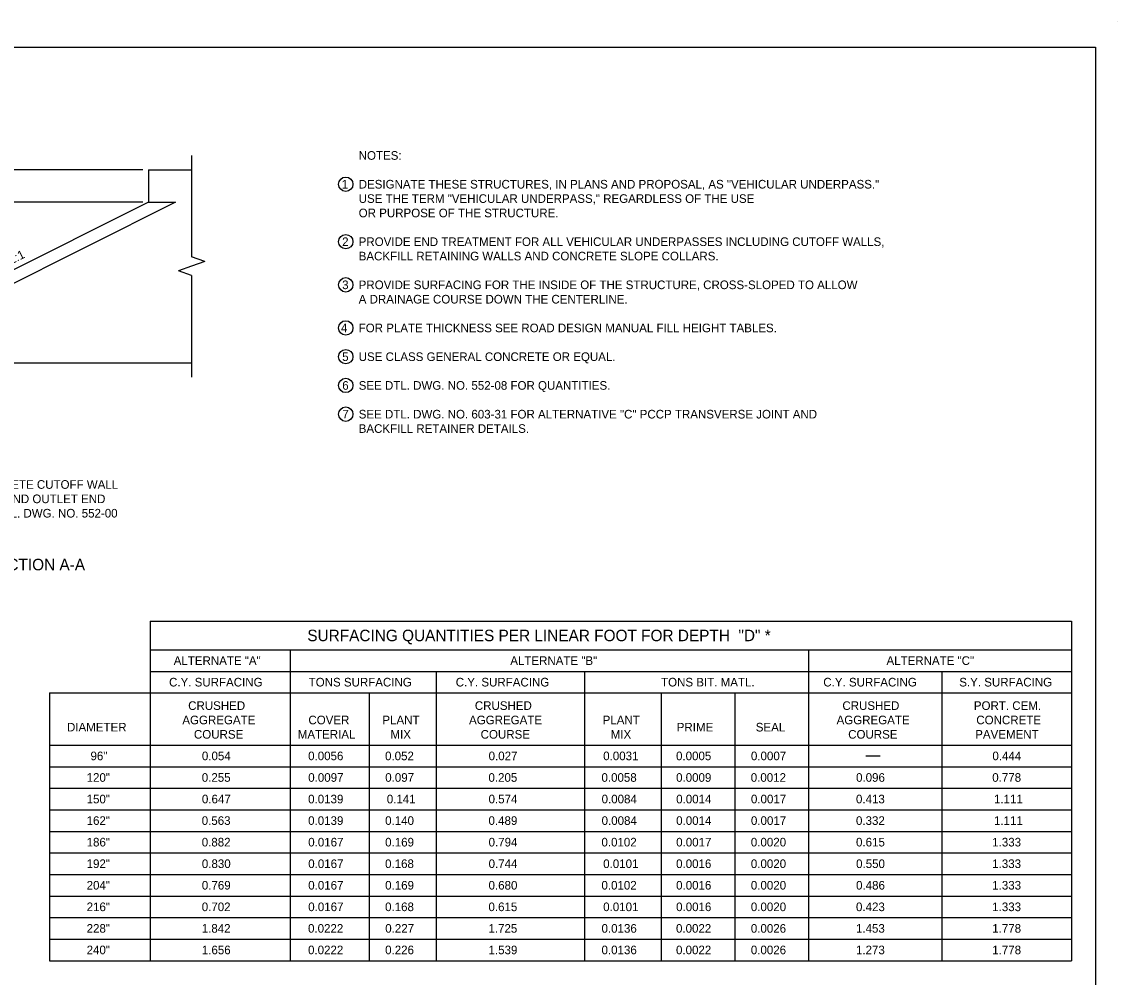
# Model space of a CAD drawing. Extents: x 49991.4 to 50021, y 49987.6 to 50011.4.
# Drawn here: x 50009.28 to 50016.9, y 49992.53 to 49999.18 of the extents above; entities that cross this region are included whole.
import ezdxf

# ---------------------------------------------------------------- set-up
doc = ezdxf.new("R2010")
doc.units = 0
for name, color, linetype in [('Level 1', 7, 'Continuous'), ('Level 2', 7, 'Continuous'), ('Level 3', 7, 'Continuous'), ('Level 6', 7, 'Continuous')]:
    doc.layers.add(name, color=color, linetype=linetype)

msp = doc.modelspace()

# ---------------------------------------------------------------- linework, layer by layer
at = {"layer": 'Level 1'}
for p, q in [((50016.9001, 49999.1756), (50016.9001, 49999.1756)), ((50010.1574, 49998.1464), (50010.1574, 49997.9206)), ((50010.1574, 49998.1464), (50010.4571, 49998.1464)), ((50010.1574, 49997.9206), (50008.3776, 49997.0307)), ((50010.3438, 49997.9206), (50008.4946, 49996.996)), ((50010.1574, 49997.9206), (50010.3438, 49997.9206)), ((50008.4946, 49996.8045), (50010.4571, 49996.8045))]:
    msp.add_line(p, q, dxfattribs=at)
msp.add_lwpolyline([(49999.3835, 49998.9992), (50016.7501, 49998.9992), (50016.7501, 49987.7988), (49999.3835, 49987.7988)], close=True, dxfattribs=at)
at = {"layer": 'Level 2'}
for p, q in [((50010.168, 49995.0069), (50016.5817, 49995.0069)), ((50010.168, 49995.0069), (50010.168, 49992.6438)), ((50016.5817, 49995.0069), (50016.5817, 49992.6438)), ((50010.168, 49994.8069), (50016.5817, 49994.8069)), ((50011.1426, 49994.8069), (50011.1426, 49992.6438)), ((50014.7527, 49994.8069), (50014.7527, 49992.6438)), ((50010.168, 49994.6569), (50016.5817, 49994.6569)), ((50012.1585, 49994.6569), (50012.1585, 49992.6438)), ((50013.1912, 49994.6569), (50013.1912, 49992.6438)), ((50015.6807, 49994.6569), (50015.6807, 49992.6438)), ((50009.468, 49994.5069), (50016.5817, 49994.5069)), ((50009.468, 49994.5069), (50009.468, 49992.6438)), ((50011.6938, 49994.5069), (50011.6938, 49992.6438)), ((50013.7256, 49994.5069), (50013.7256, 49992.6438)), ((50014.2383, 49994.5069), (50014.2383, 49992.6438)), ((50009.468, 49994.1438), (50016.5817, 49994.1438)), ((50015.1505, 49994.0688), (50015.2496, 49994.0688)), ((50009.468, 49993.9938), (50016.5817, 49993.9938)), ((50009.468, 49993.8438), (50016.5817, 49993.8438)), ((50009.468, 49993.6938), (50016.5817, 49993.6938)), ((50009.468, 49993.5438), (50016.5817, 49993.5438)), ((50009.468, 49993.3938), (50016.5817, 49993.3938)), ((50009.468, 49993.2438), (50016.5817, 49993.2438)), ((50009.468, 49993.0938), (50016.5817, 49993.0938)), ((50009.468, 49992.9438), (50016.5817, 49992.9438)), ((50009.468, 49992.7938), (50016.5817, 49992.7938)), ((50009.468, 49992.6438), (50016.5817, 49992.6438))]:
    msp.add_line(p, q, dxfattribs=at)
for centre in [(50011.5303, 49998.0464), (50011.5303, 49997.6464), (50011.5303, 49997.3464), (50011.5303, 49997.0464), (50011.5303, 49996.8464), (50011.5303, 49996.6464), (50011.5303, 49996.4464)]:
    msp.add_circle(centre, 0.05, dxfattribs=at)
at = {"layer": 'Level 3'}
for p, q in [((50010.1174, 49998.1464), (50008.0477, 49998.1464)), ((50010.1174, 49997.9206), (50008.0477, 49997.9206))]:
    msp.add_line(p, q, dxfattribs=at)
at = {"layer": 'Level 6'}
for p, q in [((50010.4571, 49998.2464), (50010.4571, 49997.5402)), ((50010.5485, 49997.5078), (50010.4571, 49997.5402)), ((50010.4571, 49997.4754), (50010.3657, 49997.443)), ((50010.5485, 49997.5078), (50010.4571, 49997.4754)), ((50010.4571, 49997.4106), (50010.3657, 49997.443)), ((50010.4571, 49997.4106), (50010.4571, 49996.7045))]:
    msp.add_line(p, q, dxfattribs=at)

# ---------------------------------------------------------------- texts
at = {"layer": 'Level 2'}
for s, height, p in [('NOTES:', 0.06, (50011.6203, 49998.2164)), ('1', 0.06, (50011.5017, 49998.0164)), ('DESIGNATE THESE STRUCTURES, IN PLANS AND PROPOSAL, AS "VEHICULAR UNDERPASS."', 0.06, (50011.6203, 49998.0164)), ('USE THE TERM "VEHICULAR UNDERPASS," REGARDLESS OF THE USE', 0.06, (50011.6203, 49997.9164)), ('OR PURPOSE OF THE STRUCTURE.', 0.06, (50011.6203, 49997.8164)), ('2', 0.06, (50011.5051, 49997.6164)), ('PROVIDE END TREATMENT FOR ALL VEHICULAR UNDERPASSES INCLUDING CUTOFF WALLS,', 0.06, (50011.6203, 49997.6164)), ('BACKFILL RETAINING WALLS AND CONCRETE SLOPE COLLARS.', 0.06, (50011.6203, 49997.5164)), ('3', 0.06, (50011.5051, 49997.3164)), ('PROVIDE SURFACING FOR THE INSIDE OF THE STRUCTURE, CROSS-SLOPED TO ALLOW', 0.06, (50011.6203, 49997.3164)), ('A DRAINAGE COURSE DOWN THE CENTERLINE.', 0.06, (50011.6203, 49997.2164)), ('4', 0.06, (50011.4966, 49997.0164)), ('FOR PLATE THICKNESS SEE ROAD DESIGN MANUAL FILL HEIGHT TABLES.', 0.06, (50011.6203, 49997.0164)), ('5', 0.06, (50011.5054, 49996.8164)), ('USE CLASS GENERAL CONCRETE OR EQUAL.', 0.06, (50011.6203, 49996.8164)), ('6', 0.06, (50011.5058, 49996.6164)), ('SEE DTL. DWG. NO. 552-08 FOR QUANTITIES.', 0.06, (50011.6203, 49996.6164)), ('7', 0.06, (50011.5065, 49996.4164)), ('SEE DTL. DWG. NO. 603-31 FOR ALTERNATIVE "C" PCCP TRANSVERSE JOINT AND', 0.06, (50011.6203, 49996.4164)), ('BACKFILL RETAINER DETAILS.', 0.06, (50011.6203, 49996.3164)), ('CONCRETE CUTOFF WALL', 0.06, (50008.9074, 49995.9273)), ('INLET AND OUTLET END', 0.06, (50008.9074, 49995.8273)), ('SEE DTL. DWG. NO. 552-00', 0.06, (50008.9074, 49995.7273)), ('SECTION A-A', 0.08, (50009.0318, 49995.3602)), ('SURFACING QUANTITIES PER LINEAR FOOT FOR DEPTH  "D" *', 0.08, (50011.2625, 49994.8669)), ('ALTERNATE "A"', 0.06, (50010.3325, 49994.7019)), ('ALTERNATE "B"', 0.06, (50012.6756, 49994.7019)), ('ALTERNATE "C"', 0.06, (50015.2947, 49994.7019)), ('C.Y. SURFACING', 0.06, (50010.3001, 49994.5519)), ('TONS SURFACING', 0.06, (50011.2721, 49994.5519)), ('C.Y. SURFACING', 0.06, (50012.2961, 49994.5519)), ('TONS BIT. MATL.', 0.06, (50013.7255, 49994.5519)), ('C.Y. SURFACING', 0.06, (50014.8548, 49994.5519)), ('S.Y. SURFACING', 0.06, (50015.8012, 49994.5519)), ('CRUSHED', 0.06, (50010.4331, 49994.3888)), ('CRUSHED', 0.06, (50012.429, 49994.3888)), ('CRUSHED', 0.06, (50014.9878, 49994.3888)), ('PORT. CEM.', 0.06, (50015.9029, 49994.3888)), ('AGGREGATE', 0.06, (50010.3925, 49994.2888)), ('COVER', 0.06, (50011.2702, 49994.2888)), ('PLANT', 0.06, (50011.7851, 49994.2888)), ('AGGREGATE', 0.06, (50012.3885, 49994.2888)), ('PLANT', 0.06, (50013.3185, 49994.2888)), ('AGGREGATE', 0.06, (50014.9473, 49994.2888)), ('CONCRETE', 0.06, (50015.92, 49994.2888)), ('DIAMETER', 0.06, (50009.5896, 49994.2388)), ('PRIME', 0.06, (50013.8345, 49994.2388)), ('SEAL', 0.06, (50014.3847, 49994.2388)), ('COURSE', 0.06, (50010.4733, 49994.1888)), ('MATERIAL', 0.06, (50011.1963, 49994.1888)), ('MIX', 0.06, (50011.8415, 49994.1888)), ('COURSE', 0.06, (50012.4693, 49994.1888)), ('MIX', 0.06, (50013.3749, 49994.1888)), ('COURSE', 0.06, (50015.0281, 49994.1888)), ('PAVEMENT', 0.06, (50015.9124, 49994.1888)), ('96"', 0.06, (50009.7531, 49994.0388)), ('0.054', 0.06, (50010.5287, 49994.0388)), ('0.0056', 0.06, (50011.2683, 49994.0388)), ('0.052', 0.06, (50011.8037, 49994.0388)), ('0.027', 0.06, (50012.5248, 49994.0388)), ('0.0031', 0.06, (50013.3225, 49994.0388)), ('0.0005', 0.06, (50013.8295, 49994.0388)), ('0.0007', 0.06, (50014.351, 49994.0388)), ('0.444', 0.06, (50016.032, 49994.0388)), ('120"', 0.06, (50009.7262, 49993.8888)), ('0.255', 0.06, (50010.5277, 49993.8888)), ('0.0097', 0.06, (50011.269, 49993.8888)), ('0.097', 0.06, (50011.8051, 49993.8888)), ('0.205', 0.06, (50012.5237, 49993.8888)), ('0.0058', 0.06, (50013.3104, 49993.8888)), ('0.0009', 0.06, (50013.8299, 49993.8888)), ('0.0012', 0.06, (50014.3496, 49993.8888)), ('0.096', 0.06, (50015.0828, 49993.8888)), ('0.778', 0.06, (50016.031, 49993.8888)), ('150"', 0.06, (50009.7262, 49993.7388)), ('0.647', 0.06, (50010.5288, 49993.7388)), ('0.0139', 0.06, (50011.2683, 49993.7388)), ('0.141', 0.06, (50011.8159, 49993.7388)), ('0.574', 0.06, (50012.5246, 49993.7388)), ('0.0084', 0.06, (50013.3114, 49993.7388)), ('0.0014', 0.06, (50013.8305, 49993.7388)), ('0.0017', 0.06, (50014.351, 49993.7388)), ('0.413', 0.06, (50015.0822, 49993.7388)), ('1.111', 0.06, (50016.0429, 49993.7388)), ('162"', 0.06, (50009.7262, 49993.5888)), ('0.563', 0.06, (50010.5274, 49993.5888)), ('0.0139', 0.06, (50011.2683, 49993.5888)), ('0.140', 0.06, (50011.8045, 49993.5888)), ('0.489', 0.06, (50012.524, 49993.5888)), ('0.0084', 0.06, (50013.3114, 49993.5888)), ('0.0014', 0.06, (50013.8305, 49993.5888)), ('0.0017', 0.06, (50014.351, 49993.5888)), ('0.332', 0.06, (50015.0822, 49993.5888)), ('1.111', 0.06, (50016.0429, 49993.5888)), ('186"', 0.06, (50009.7262, 49993.4388)), ('0.882', 0.06, (50010.5275, 49993.4388)), ('0.0167', 0.06, (50011.269, 49993.4388)), ('0.169', 0.06, (50011.8044, 49993.4388)), ('0.794', 0.06, (50012.5247, 49993.4388)), ('0.0102', 0.06, (50013.3102, 49993.4388)), ('0.0017', 0.06, (50013.8306, 49993.4388)), ('0.0020', 0.06, (50014.3504, 49993.4388)), ('0.615', 0.06, (50015.0825, 49993.4388)), ('1.333', 0.06, (50016.0308, 49993.4388)), ('192"', 0.06, (50009.7262, 49993.2888)), ('0.830', 0.06, (50010.5284, 49993.2888)), ('0.0167', 0.06, (50011.269, 49993.2888)), ('0.168', 0.06, (50011.8039, 49993.2888)), ('0.744', 0.06, (50012.5247, 49993.2888)), ('0.0101', 0.06, (50013.3225, 49993.2888)), ('0.0016', 0.06, (50013.83, 49993.2888)), ('0.0020', 0.06, (50014.3504, 49993.2888)), ('0.550', 0.06, (50015.0831, 49993.2888)), ('1.333', 0.06, (50016.0308, 49993.2888)), ('204"', 0.06, (50009.7262, 49993.1388)), ('0.769', 0.06, (50010.5282, 49993.1388)), ('0.0167', 0.06, (50011.269, 49993.1388)), ('0.169', 0.06, (50011.8044, 49993.1388)), ('0.680', 0.06, (50012.5244, 49993.1388)), ('0.0102', 0.06, (50013.3102, 49993.1388)), ('0.0016', 0.06, (50013.83, 49993.1388)), ('0.0020', 0.06, (50014.3504, 49993.1388)), ('0.486', 0.06, (50015.0829, 49993.1388)), ('1.333', 0.06, (50016.0308, 49993.1388)), ('216"', 0.06, (50009.7262, 49992.9888)), ('0.702', 0.06, (50010.5275, 49992.9888)), ('0.0167', 0.06, (50011.269, 49992.9888)), ('0.168', 0.06, (50011.8039, 49992.9888)), ('0.615', 0.06, (50012.5238, 49992.9888)), ('0.0101', 0.06, (50013.3225, 49992.9888)), ('0.0016', 0.06, (50013.83, 49992.9888)), ('0.0020', 0.06, (50014.3504, 49992.9888)), ('0.423', 0.06, (50015.0823, 49992.9888)), ('1.333', 0.06, (50016.0308, 49992.9888)), ('228"', 0.06, (50009.7262, 49992.8388)), ('1.842', 0.06, (50010.5275, 49992.8388)), ('0.0222', 0.06, (50011.2676, 49992.8388)), ('0.227', 0.06, (50011.8051, 49992.8388)), ('1.725', 0.06, (50012.5237, 49992.8388)), ('0.0136', 0.06, (50013.3109, 49992.8388)), ('0.0022', 0.06, (50013.8293, 49992.8388)), ('0.0026', 0.06, (50014.3503, 49992.8388)), ('1.453', 0.06, (50015.0822, 49992.8388)), ('1.778', 0.06, (50016.031, 49992.8388)), ('240"', 0.06, (50009.7262, 49992.6888)), ('1.656', 0.06, (50010.5282, 49992.6888)), ('0.0222', 0.06, (50011.2676, 49992.6888)), ('0.226', 0.06, (50011.8044, 49992.6888)), ('1.539', 0.06, (50012.5241, 49992.6888)), ('0.0136', 0.06, (50013.3109, 49992.6888)), ('0.0022', 0.06, (50013.8293, 49992.6888)), ('0.0026', 0.06, (50014.3503, 49992.6888)), ('1.273', 0.06, (50015.0822, 49992.6888)), ('1.778', 0.06, (50016.031, 49992.6888))]:
    msp.add_text(s, height=height, dxfattribs=at).set_placement(p)
msp.add_text('2:1', height=0.06, rotation=26.56505, dxfattribs=at).set_placement((50009.2023, 49997.4878))

doc.saveas('drawing.dxf')
